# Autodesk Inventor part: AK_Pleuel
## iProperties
Created: 2004-01
Part Number: AK_Pleuel
Material: Aluminium - 6061
Document SubType Name: Modellieren
Designer: Ulrich
Control State: 0
Master: False
Checked Out: False
Shininess: 20.0
Angle Display Precision: 2
Document Length Units: 11269
Document Angle Units: 11279
Document Time Units: 11290
Document Mass Units: 11283
Document Length Units Precision: 3
Document Angle Units Precision: 2
Density: 0.0
Volumn: 0.0
Area: 0.0
PropertySet Name: Model Information
Author: Ulrich
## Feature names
1. Grundkörper [Extrusion]
2. Pleuelauge_Ak [Hole]
3. Pleuelauge_Kw [Hole]
